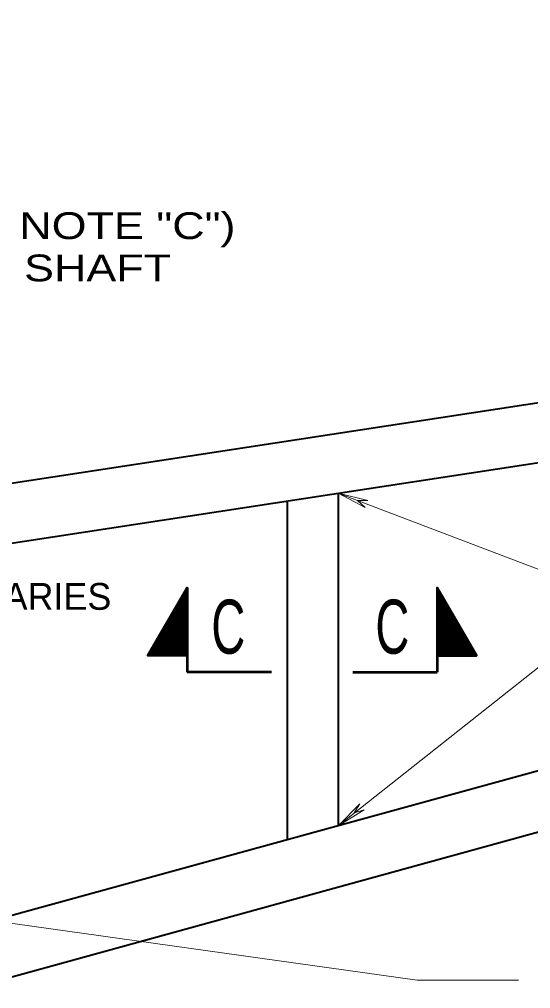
# Model space of a CAD drawing. Extents: x 312583 to 312854, y 144419 to 144597.
# Drawn here: x 312748.5 to 312762.98, y 144538.22 to 144565.69 of the extents above; entities that cross this region are included whole.
import ezdxf
from ezdxf.enums import TextEntityAlignment as Align

# ---------------------------------------------------------------- set-up
doc = ezdxf.new("R2010")
doc.units = 0
doc.header["$LTSCALE"] = 0.3
doc.layers.add('1', color=7, linetype='Continuous', lineweight=13)

msp = doc.modelspace()

# ---------------------------------------------------------------- linework, layer by layer
at = {"layer": '1', "lineweight": 40}
for p, q in [((312730.935, 144549.8976), (312834.251, 144565.6909)), ((312730.935, 144548.1956), (312834.504, 144564.0272)), ((312730.935, 144535.5226), (312830.111, 144562.8236)), ((312730.9427, 144533.7822), (312830.5557, 144561.2059)), ((312757.5307, 144552.2589), (312757.5307, 144542.8366)), ((312756.0894, 144552.0442), (312756.0894, 144542.4456))]:
    msp.add_line(p, q, dxfattribs=at)
at = {"layer": '1'}
for p, q in [((312757.5307, 144552.2589), (312758.2974, 144551.8526)), ((312757.5307, 144552.2589), (312758.374, 144552.0519)), ((312758.2974, 144551.8526), (312758.0827, 144552.0519)), ((312758.374, 144552.0519), (312758.0827, 144552.0519)), ((312757.5307, 144542.8366), (312758.144, 144543.4576)), ((312758.144, 144543.4576), (312757.9907, 144543.2046)), ((312757.5307, 144542.8366), (312758.2744, 144543.2889)), ((312758.2744, 144543.2889), (312757.9907, 144543.2046)), ((312759.7694, 144538.4589), (312762.6444, 144538.4589))]:
    msp.add_line(p, q, dxfattribs=at)
at = {"layer": '1', "lineweight": 35}
for p, q in [((312753.2527, 144549.3686), (312753.1607, 144549.4222)), ((312753.2527, 144549.3992), (312753.1684, 144549.4452)), ((312753.2527, 144549.4299), (312753.1837, 144549.4682)), ((312753.2527, 144549.4529), (312753.1914, 144549.4836)), ((312753.2527, 144549.4836), (312753.2067, 144549.5066)), ((312753.2527, 144549.5066), (312753.2144, 144549.5296)), ((312753.2527, 144549.5372), (312753.2297, 144549.5449)), ((312753.2527, 144549.5679), (312753.2374, 144549.5679)), ((312760.3367, 144549.5679), (312760.352, 144549.5679)), ((312760.3367, 144549.5372), (312760.3597, 144549.5449)), ((312760.3367, 144549.5066), (312760.375, 144549.5296)), ((312760.3367, 144549.4836), (312760.3827, 144549.5066)), ((312760.3367, 144549.4529), (312760.398, 144549.4836)), ((312760.3367, 144549.4299), (312760.4057, 144549.4682)), ((312760.3367, 144549.3992), (312760.421, 144549.4452)), ((312760.3367, 144549.3686), (312760.4287, 144549.4222)), ((312753.2527, 144549.0082), (312752.9997, 144549.1539)), ((312753.2527, 144549.0389), (312753.015, 144549.1769)), ((312753.2527, 144549.0696), (312753.0227, 144549.1999)), ((312753.2527, 144549.0926), (312753.038, 144549.2152)), ((312753.2527, 144549.1232), (312753.0457, 144549.2382)), ((312753.2527, 144549.1462), (312753.061, 144549.2612)), ((312753.2527, 144549.1769), (312753.0764, 144549.2766)), ((312753.2527, 144549.2076), (312753.084, 144549.2996)), ((312753.2527, 144549.2382), (312753.0994, 144549.3226)), ((312753.2527, 144549.2612), (312753.1147, 144549.3379)), ((312753.2527, 144549.2919), (312753.1224, 144549.3609)), ((312753.2527, 144549.3149), (312753.1377, 144549.3839)), ((312753.2527, 144549.3379), (312753.1454, 144549.4069)), ((312760.3367, 144549.3379), (312760.444, 144549.4069)), ((312760.3367, 144549.3149), (312760.4517, 144549.3839)), ((312760.3367, 144549.2919), (312760.467, 144549.3609)), ((312760.3367, 144549.2612), (312760.4747, 144549.3379)), ((312760.3367, 144549.2382), (312760.49, 144549.3226)), ((312760.3367, 144549.2076), (312760.5054, 144549.2996)), ((312760.3367, 144549.1769), (312760.513, 144549.2766)), ((312760.3367, 144549.1462), (312760.5284, 144549.2612)), ((312760.3367, 144549.1232), (312760.5437, 144549.2382)), ((312760.3367, 144549.0926), (312760.5514, 144549.2152)), ((312760.3367, 144549.0696), (312760.5667, 144549.1999)), ((312760.3367, 144549.0389), (312760.5744, 144549.1769)), ((312760.3367, 144549.0082), (312760.5897, 144549.1539)), ((312753.2527, 144548.6479), (312752.8464, 144548.8856)), ((312753.2527, 144548.6786), (312752.854, 144548.9086)), ((312753.2527, 144548.7092), (312752.8694, 144548.9239)), ((312753.2527, 144548.7399), (312752.8847, 144548.9469)), ((312753.2527, 144548.7629), (312752.8924, 144548.9699)), ((312753.2527, 144548.7936), (312752.9077, 144548.9852)), ((312753.2527, 144548.8166), (312752.923, 144549.0082)), ((312753.2527, 144548.8472), (312752.9307, 144549.0312)), ((312753.2527, 144548.8702), (312752.946, 144549.0466)), ((312753.2527, 144548.9009), (312752.9537, 144549.0696)), ((312753.2527, 144548.9316), (312752.969, 144549.0926)), ((312753.2527, 144548.9546), (312752.9767, 144549.1079)), ((312753.2527, 144548.9852), (312752.992, 144549.1386)), ((312760.3367, 144548.9852), (312760.5974, 144549.1386)), ((312760.3367, 144548.9546), (312760.6127, 144549.1079)), ((312760.3367, 144548.9316), (312760.6204, 144549.0926)), ((312760.3367, 144548.9009), (312760.6357, 144549.0696)), ((312760.3367, 144548.8702), (312760.6434, 144549.0466)), ((312760.3367, 144548.8472), (312760.6587, 144549.0312)), ((312760.3367, 144548.8166), (312760.6664, 144549.0082)), ((312760.3367, 144548.7936), (312760.6817, 144548.9852)), ((312760.3367, 144548.7629), (312760.697, 144548.9699)), ((312760.3367, 144548.7399), (312760.7047, 144548.9469)), ((312760.3367, 144548.7092), (312760.72, 144548.9239)), ((312760.3367, 144548.6786), (312760.7354, 144548.9086)), ((312760.3367, 144548.6479), (312760.743, 144548.8856)), ((312753.2527, 144548.2952), (312752.693, 144548.6096)), ((312753.245, 144548.3182), (312752.7007, 144548.6402)), ((312753.2527, 144548.3489), (312752.716, 144548.6556)), ((312753.2527, 144548.3719), (312752.7314, 144548.6786)), ((312753.2527, 144548.4026), (312752.739, 144548.7016)), ((312753.2527, 144548.4332), (312752.7544, 144548.7169)), ((312753.2527, 144548.4562), (312752.762, 144548.7399)), ((312753.2527, 144548.4869), (312752.7774, 144548.7629)), ((312753.2527, 144548.5176), (312752.785, 144548.7782)), ((312753.2527, 144548.5406), (312752.8004, 144548.8012)), ((312753.2527, 144548.5712), (312752.808, 144548.8242)), ((312753.2527, 144548.6019), (312752.8234, 144548.8396)), ((312753.2527, 144548.6249), (312752.831, 144548.8626)), ((312760.3367, 144548.6249), (312760.7584, 144548.8626)), ((312760.3367, 144548.6019), (312760.766, 144548.8396)), ((312760.3367, 144548.5712), (312760.7814, 144548.8242)), ((312760.3367, 144548.5406), (312760.789, 144548.8012)), ((312760.3367, 144548.5176), (312760.8044, 144548.7782)), ((312760.3367, 144548.4869), (312760.812, 144548.7629)), ((312760.3367, 144548.4562), (312760.8274, 144548.7399)), ((312760.3367, 144548.4332), (312760.835, 144548.7169)), ((312760.3367, 144548.4026), (312760.8504, 144548.7016)), ((312760.3367, 144548.3719), (312760.858, 144548.6786)), ((312760.3367, 144548.3489), (312760.8734, 144548.6556)), ((312760.3367, 144548.2952), (312760.8964, 144548.6096)), ((312760.3444, 144548.3182), (312760.8887, 144548.6402)), ((312753.2527, 144547.9042), (312752.5244, 144548.3259)), ((312753.2527, 144547.9349), (312752.5397, 144548.3412)), ((312753.2527, 144547.9579), (312752.5474, 144548.3642)), ((312753.2527, 144547.9886), (312752.5627, 144548.3872)), ((312753.2527, 144548.0192), (312752.578, 144548.4102)), ((312753.2527, 144548.0422), (312752.5857, 144548.4256)), ((312753.245, 144548.0729), (312752.601, 144548.4486)), ((312753.2527, 144548.1036), (312752.6087, 144548.4716)), ((312753.2527, 144548.1266), (312752.624, 144548.4869)), ((312753.2527, 144548.1496), (312752.6317, 144548.5099)), ((312753.2527, 144548.1802), (312752.647, 144548.5329)), ((312753.2527, 144548.2109), (312752.6547, 144548.5482)), ((312753.2527, 144548.2416), (312752.67, 144548.5712)), ((312753.2527, 144548.2646), (312752.6777, 144548.5942)), ((312760.3367, 144548.2646), (312760.9117, 144548.5942)), ((312760.3367, 144548.2416), (312760.9194, 144548.5712)), ((312760.3367, 144548.2109), (312760.9347, 144548.5482)), ((312760.3367, 144548.1802), (312760.9424, 144548.5329)), ((312760.3367, 144548.1496), (312760.9577, 144548.5099)), ((312760.3367, 144548.1266), (312760.9654, 144548.4869)), ((312760.3367, 144548.1036), (312760.9807, 144548.4716)), ((312760.3367, 144548.0422), (312761.0037, 144548.4256)), ((312760.3367, 144548.0192), (312761.0114, 144548.4102)), ((312760.3367, 144547.9886), (312761.0267, 144548.3872)), ((312760.3367, 144547.9579), (312761.042, 144548.3642)), ((312760.3367, 144547.9349), (312761.0497, 144548.3412)), ((312760.3367, 144547.9042), (312761.065, 144548.3259)), ((312760.3444, 144548.0729), (312760.9884, 144548.4486)), ((312753.038, 144547.6666), (312752.371, 144548.0499)), ((312753.084, 144547.6666), (312752.3864, 144548.0729)), ((312753.1377, 144547.6666), (312752.394, 144548.0959)), ((312753.176, 144547.6666), (312752.4094, 144548.1112)), ((312753.2297, 144547.6666), (312752.417, 144548.1419)), ((312753.2527, 144547.6819), (312752.4324, 144548.1572)), ((312753.2527, 144547.7126), (312752.44, 144548.1802)), ((312753.2527, 144547.7432), (312752.4554, 144548.2032)), ((312753.2527, 144547.7662), (312752.463, 144548.2186)), ((312753.2527, 144547.7969), (312752.4784, 144548.2416)), ((312753.245, 144547.8199), (312752.486, 144548.2646)), ((312753.245, 144547.8506), (312752.5014, 144548.2799)), ((312753.2527, 144547.8736), (312752.509, 144548.3029)), ((312760.3367, 144547.8736), (312761.0804, 144548.3029)), ((312760.3367, 144547.7969), (312761.111, 144548.2416)), ((312760.3367, 144547.7662), (312761.1264, 144548.2186)), ((312760.3367, 144547.7432), (312761.134, 144548.2032)), ((312760.3367, 144547.7126), (312761.1494, 144548.1802)), ((312760.3367, 144547.6819), (312761.157, 144548.1572)), ((312760.3444, 144547.8506), (312761.088, 144548.2799)), ((312760.3444, 144547.8199), (312761.1034, 144548.2646)), ((312760.3597, 144547.6666), (312761.1724, 144548.1419)), ((312760.4134, 144547.6666), (312761.18, 144548.1112)), ((312760.4517, 144547.6666), (312761.1954, 144548.0959)), ((312760.5054, 144547.6666), (312761.203, 144548.0729)), ((312760.5514, 144547.6666), (312761.2184, 144548.0499)), ((312752.4094, 144547.6666), (312752.2177, 144547.7816)), ((312752.463, 144547.6666), (312752.2254, 144547.8046)), ((312752.509, 144547.6666), (312752.2407, 144547.8276)), ((312752.555, 144547.6666), (312752.2484, 144547.8429)), ((312752.601, 144547.6666), (312752.2637, 144547.8736)), ((312752.6547, 144547.6666), (312752.2714, 144547.8889)), ((312752.7007, 144547.6666), (312752.2867, 144547.9119)), ((312752.7467, 144547.6666), (312752.2944, 144547.9349)), ((312752.8004, 144547.6666), (312752.3097, 144547.9502)), ((312752.8464, 144547.6666), (312752.3174, 144547.9732)), ((312752.8924, 144547.6666), (312752.3327, 144547.9886)), ((312752.946, 144547.6666), (312752.348, 144548.0116)), ((312752.992, 144547.6666), (312752.3557, 144548.0346)), ((312760.5974, 144547.6666), (312761.2337, 144548.0346)), ((312760.6434, 144547.6666), (312761.2414, 144548.0116)), ((312760.697, 144547.6666), (312761.2567, 144547.9886)), ((312760.743, 144547.6666), (312761.272, 144547.9732)), ((312760.789, 144547.6666), (312761.2797, 144547.9502)), ((312760.8427, 144547.6666), (312761.295, 144547.9349)), ((312760.8887, 144547.6666), (312761.3027, 144547.9119)), ((312760.9347, 144547.6666), (312761.318, 144547.8889)), ((312760.9884, 144547.6666), (312761.3257, 144547.8736)), ((312761.0344, 144547.6666), (312761.341, 144547.8429)), ((312761.0804, 144547.6666), (312761.3487, 144547.8276)), ((312761.1264, 144547.6666), (312761.364, 144547.8046)), ((312761.18, 144547.6666), (312761.3717, 144547.7816)), ((312752.1717, 144547.6666), (312752.1564, 144547.6819)), ((312752.2177, 144547.6666), (312752.164, 144547.7049)), ((312752.2714, 144547.6666), (312752.1794, 144547.7202)), ((312752.3174, 144547.6666), (312752.1947, 144547.7432)), ((312752.371, 144547.6666), (312752.2024, 144547.7662)), ((312761.2184, 144547.6666), (312761.387, 144547.7662)), ((312761.272, 144547.6666), (312761.3947, 144547.7432)), ((312761.318, 144547.6666), (312761.41, 144547.7202)), ((312761.3717, 144547.6666), (312761.4254, 144547.7049)), ((312761.4177, 144547.6666), (312761.433, 144547.6819))]:
    msp.add_line(p, q, dxfattribs=at)
at = {"layer": '1', "lineweight": 53}
for p, q in [((312753.2527, 144547.6666), (312753.2527, 144547.1912)), ((312760.3367, 144547.6666), (312760.3367, 144547.1912)), ((312755.6447, 144547.1912), (312753.2527, 144547.1912)), ((312757.9447, 144547.1912), (312760.3367, 144547.1912))]:
    msp.add_line(p, q, dxfattribs=at)
at = {"layer": '1'}
for points in [[(312757.5307, 144542.8366), (312765.573, 144549.1999), (312757.5307, 144552.2589)], [(312759.7694, 144538.4589), (312733.488, 144542.1466), (312730.9274, 144544.5539)]]:
    msp.add_lwpolyline(points, dxfattribs=at)
at = {"layer": '1', "lineweight": 53}
for points in [[(312753.2527, 144547.6666), (312752.141, 144547.6666), (312753.2527, 144549.5832)], [(312760.3367, 144547.6666), (312761.4484, 144547.6666), (312760.3367, 144549.5832)]]:
    msp.add_lwpolyline(points, close=True, dxfattribs=at)

# ---------------------------------------------------------------- texts
at = {"layer": '1', "width": 1.25}
for s, p in [('ALLOY 356-T6 (SEE NOTE "C")', (312736.3554, 144559.4636)), ('TO FIT 229 MM O.D. SHAFT', (312736.3554, 144558.2666))]:
    msp.add_text(s, height=0.76, dxfattribs=at).set_placement(p)
at = {"layer": '1'}
msp.add_text('VARIES', height=0.76, dxfattribs=at).set_placement((312747.3802, 144548.9574))
at = {"layer": '1', "width": 0.65}
for p in [(312754.4219, 144547.7126), (312759.0679, 144547.7126)]:
    msp.add_text('C', height=1.533, dxfattribs=at).set_placement(p, align=Align.CENTER)

doc.saveas('drawing.dxf')
